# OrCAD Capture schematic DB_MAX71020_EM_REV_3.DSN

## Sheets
1 01. Revision History and Notes: title: DB71020 - Revision History and Notes; rev: 2.0; note: ART3 Utility; note: Copyright © 2014 - Maxim Integrated Products
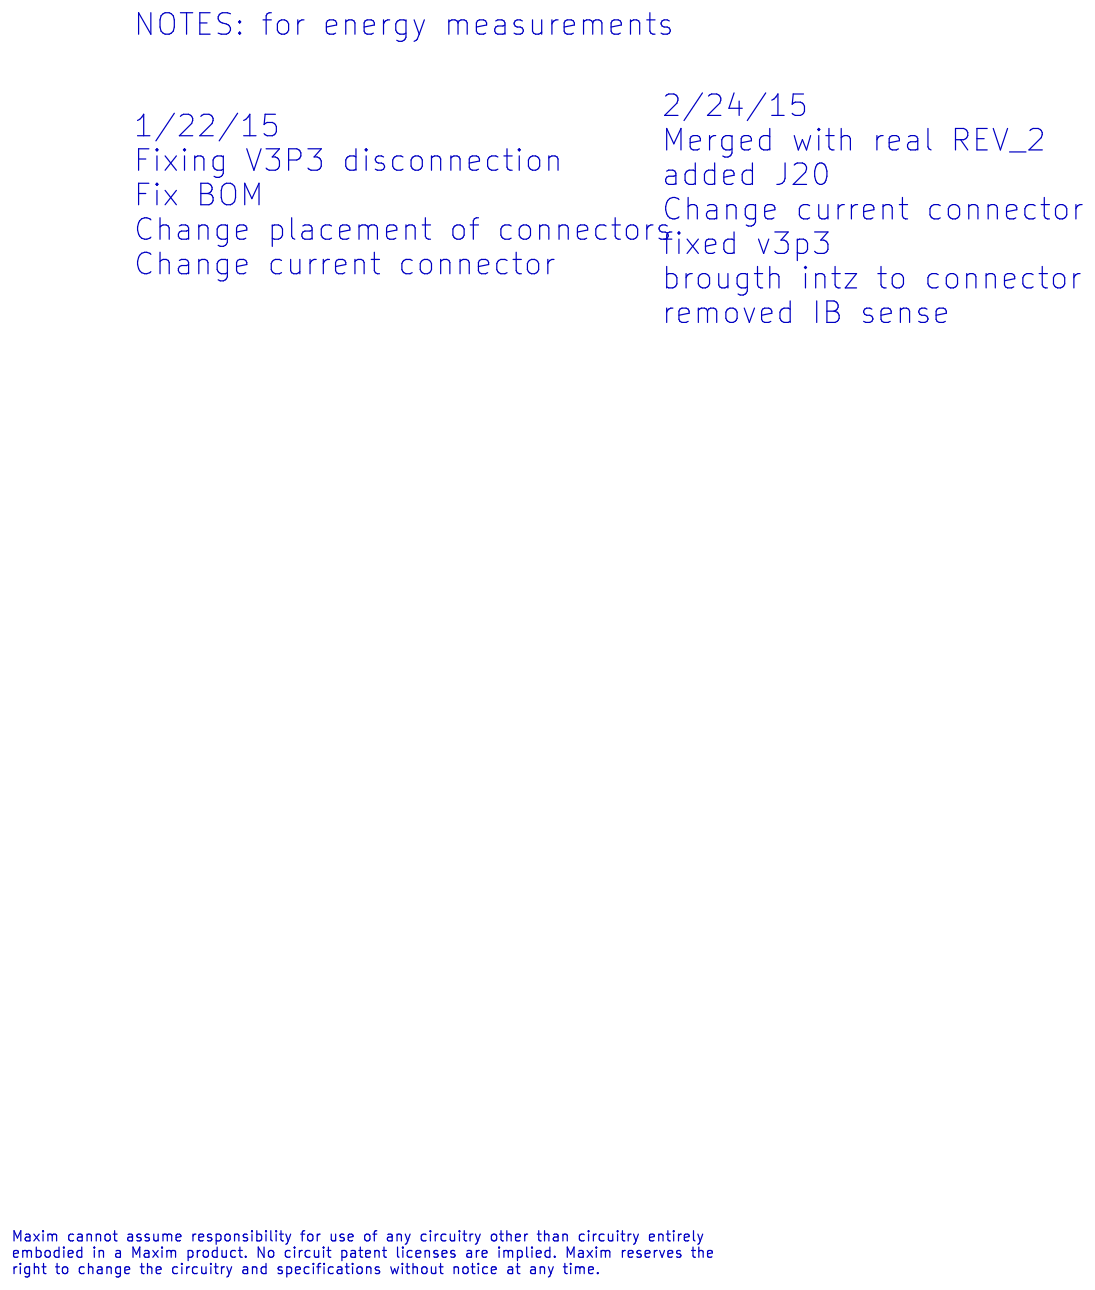
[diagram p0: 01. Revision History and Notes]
2 02. MAX71020: size B; title: DB71020 - AM48; rev: A
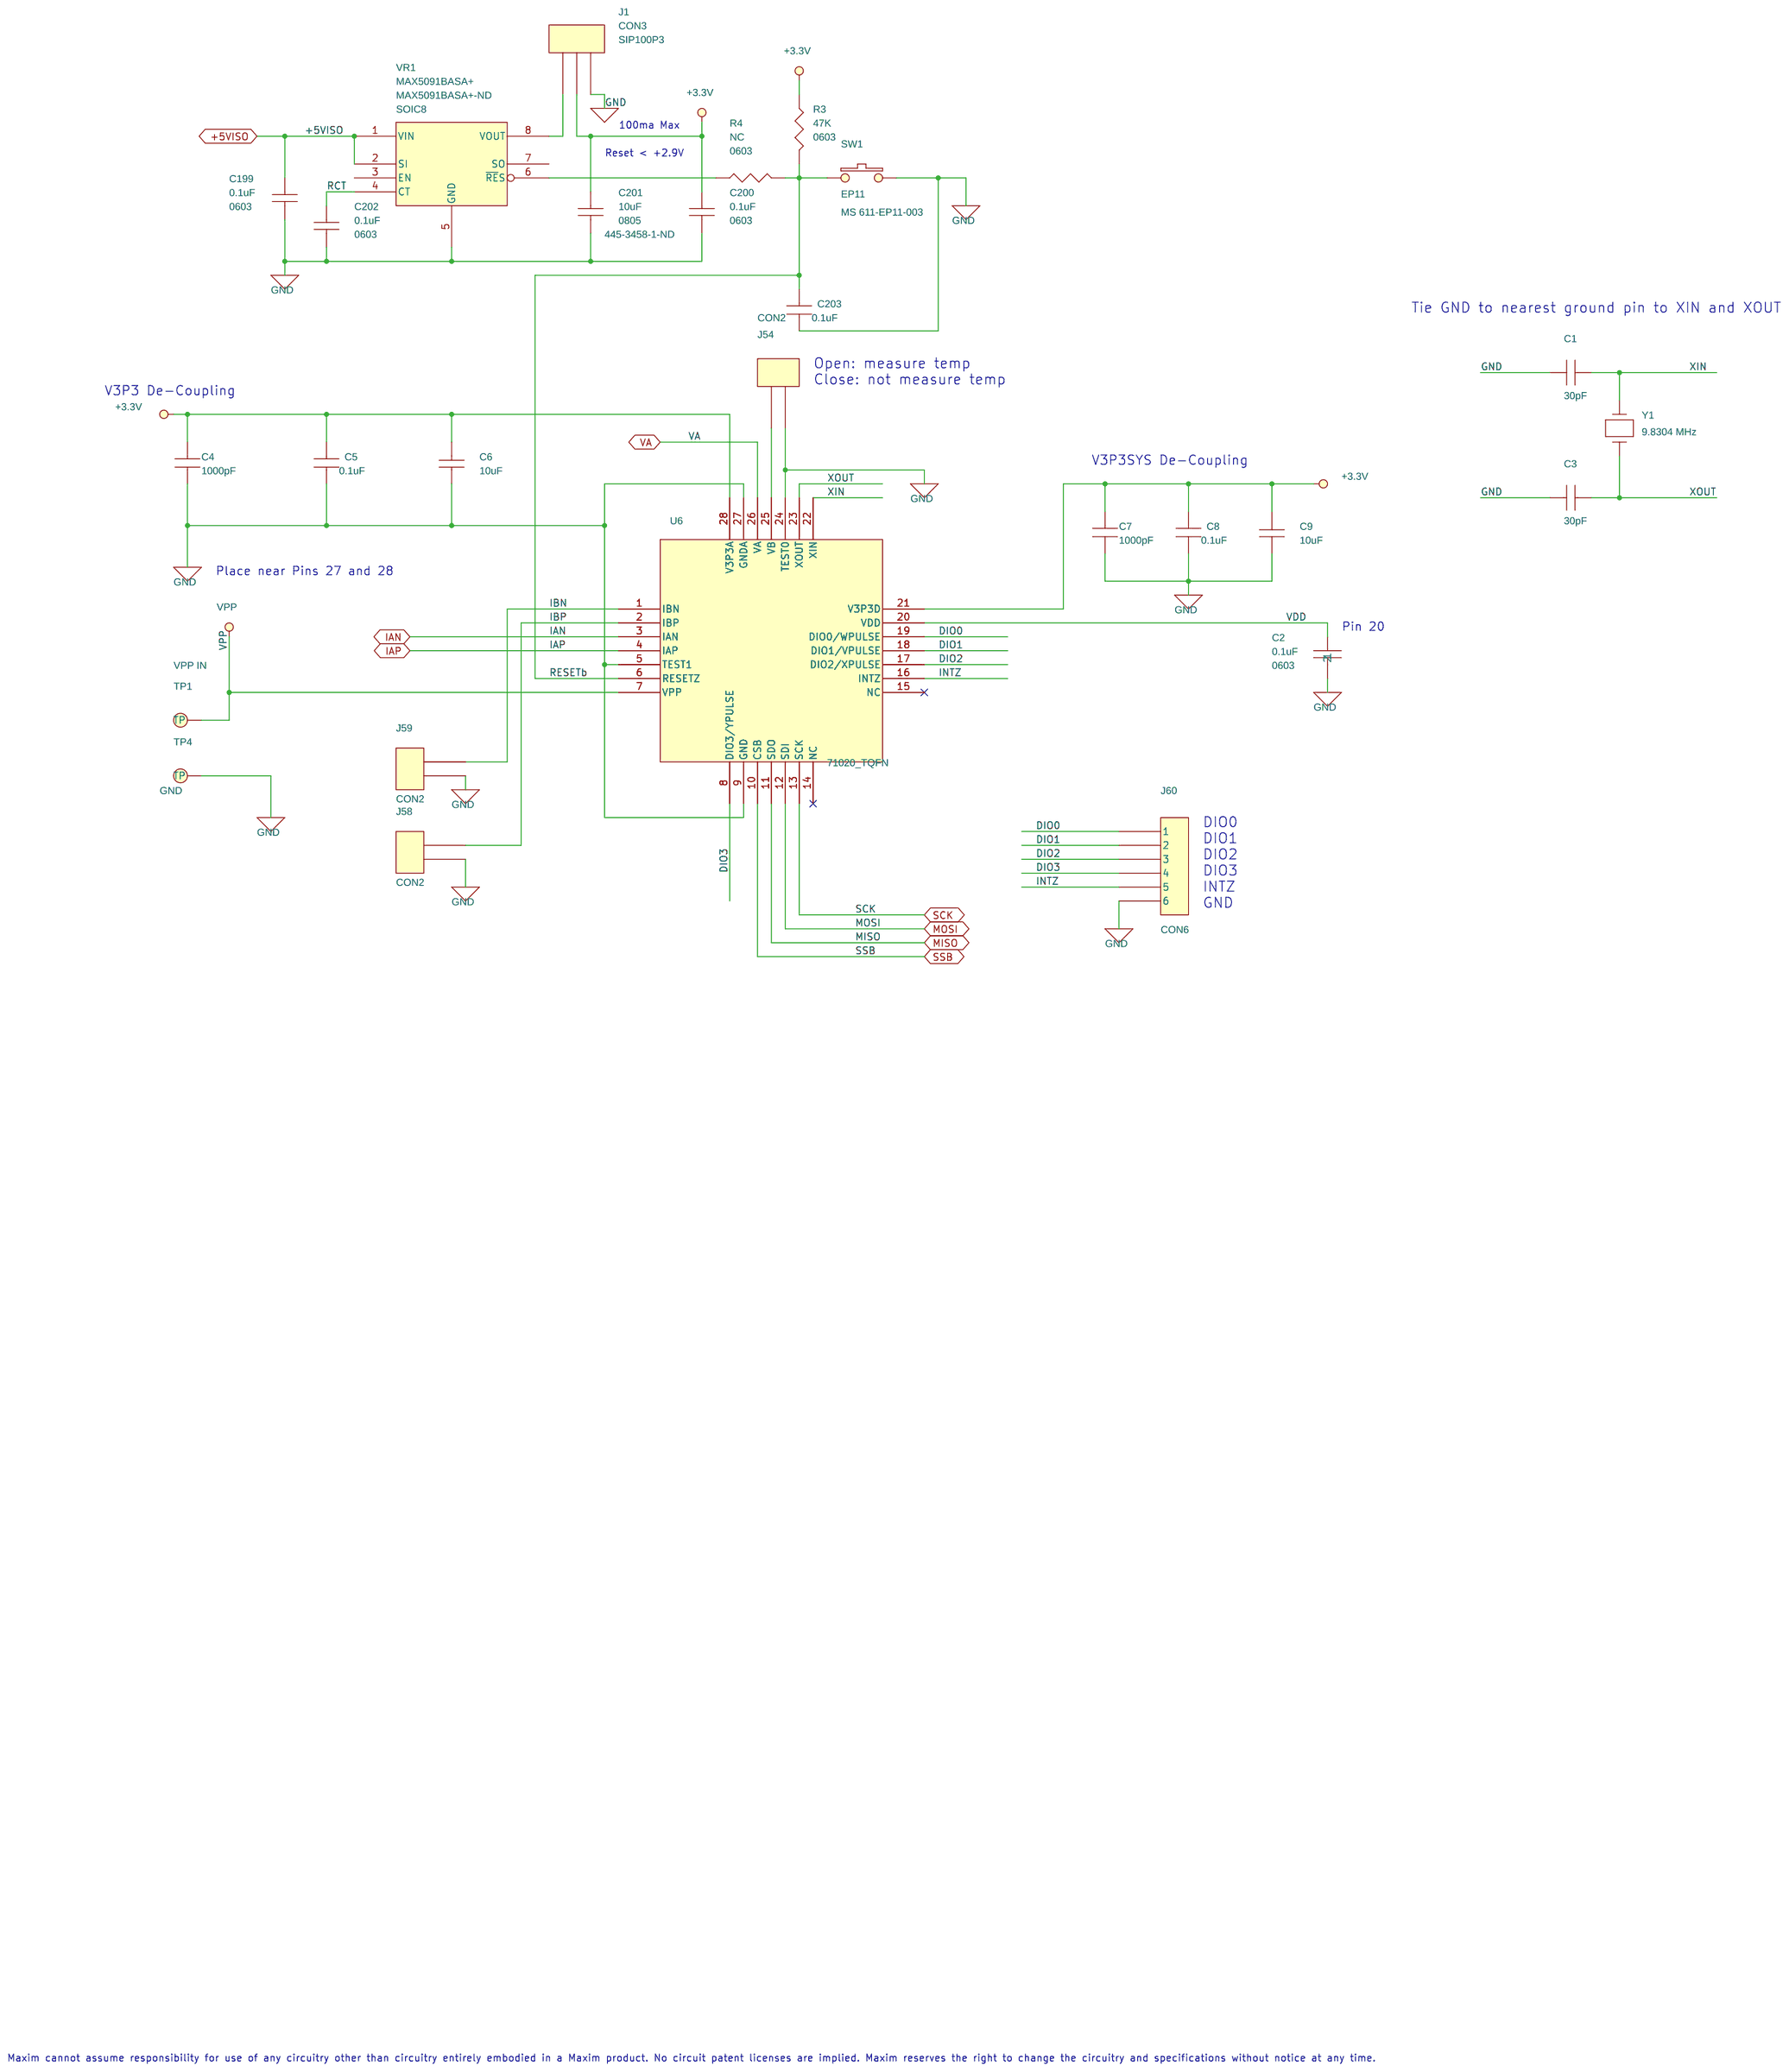
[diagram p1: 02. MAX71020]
3 03. Isolated USB to UART: size B; title: DB71020 - AM48
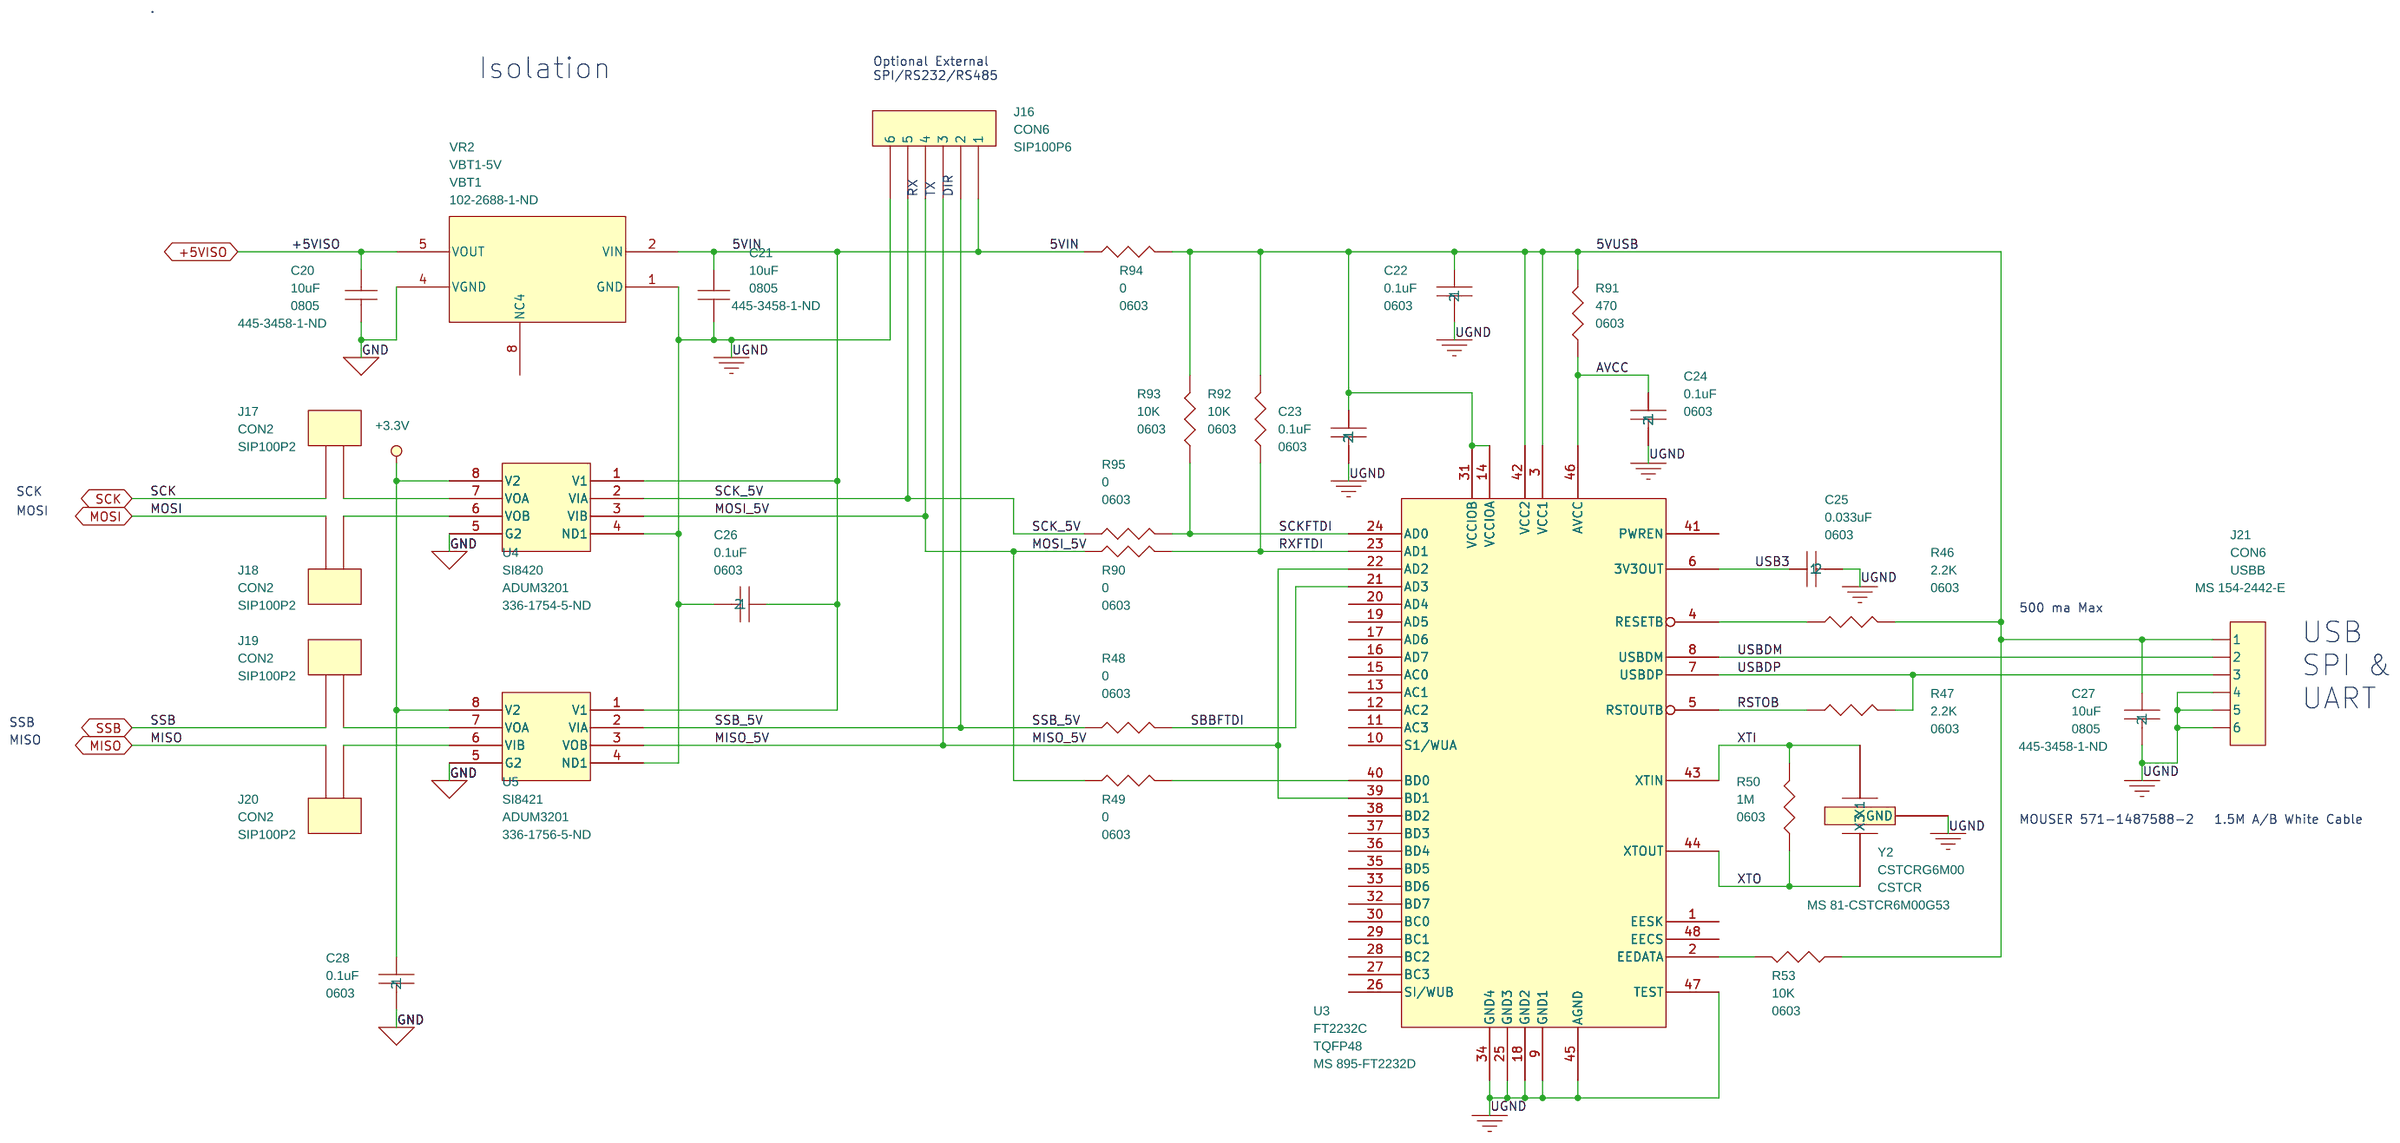
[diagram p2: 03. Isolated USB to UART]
4 04. Sensors: size Custom; title: DB71020 - Current & Voltage Sensors
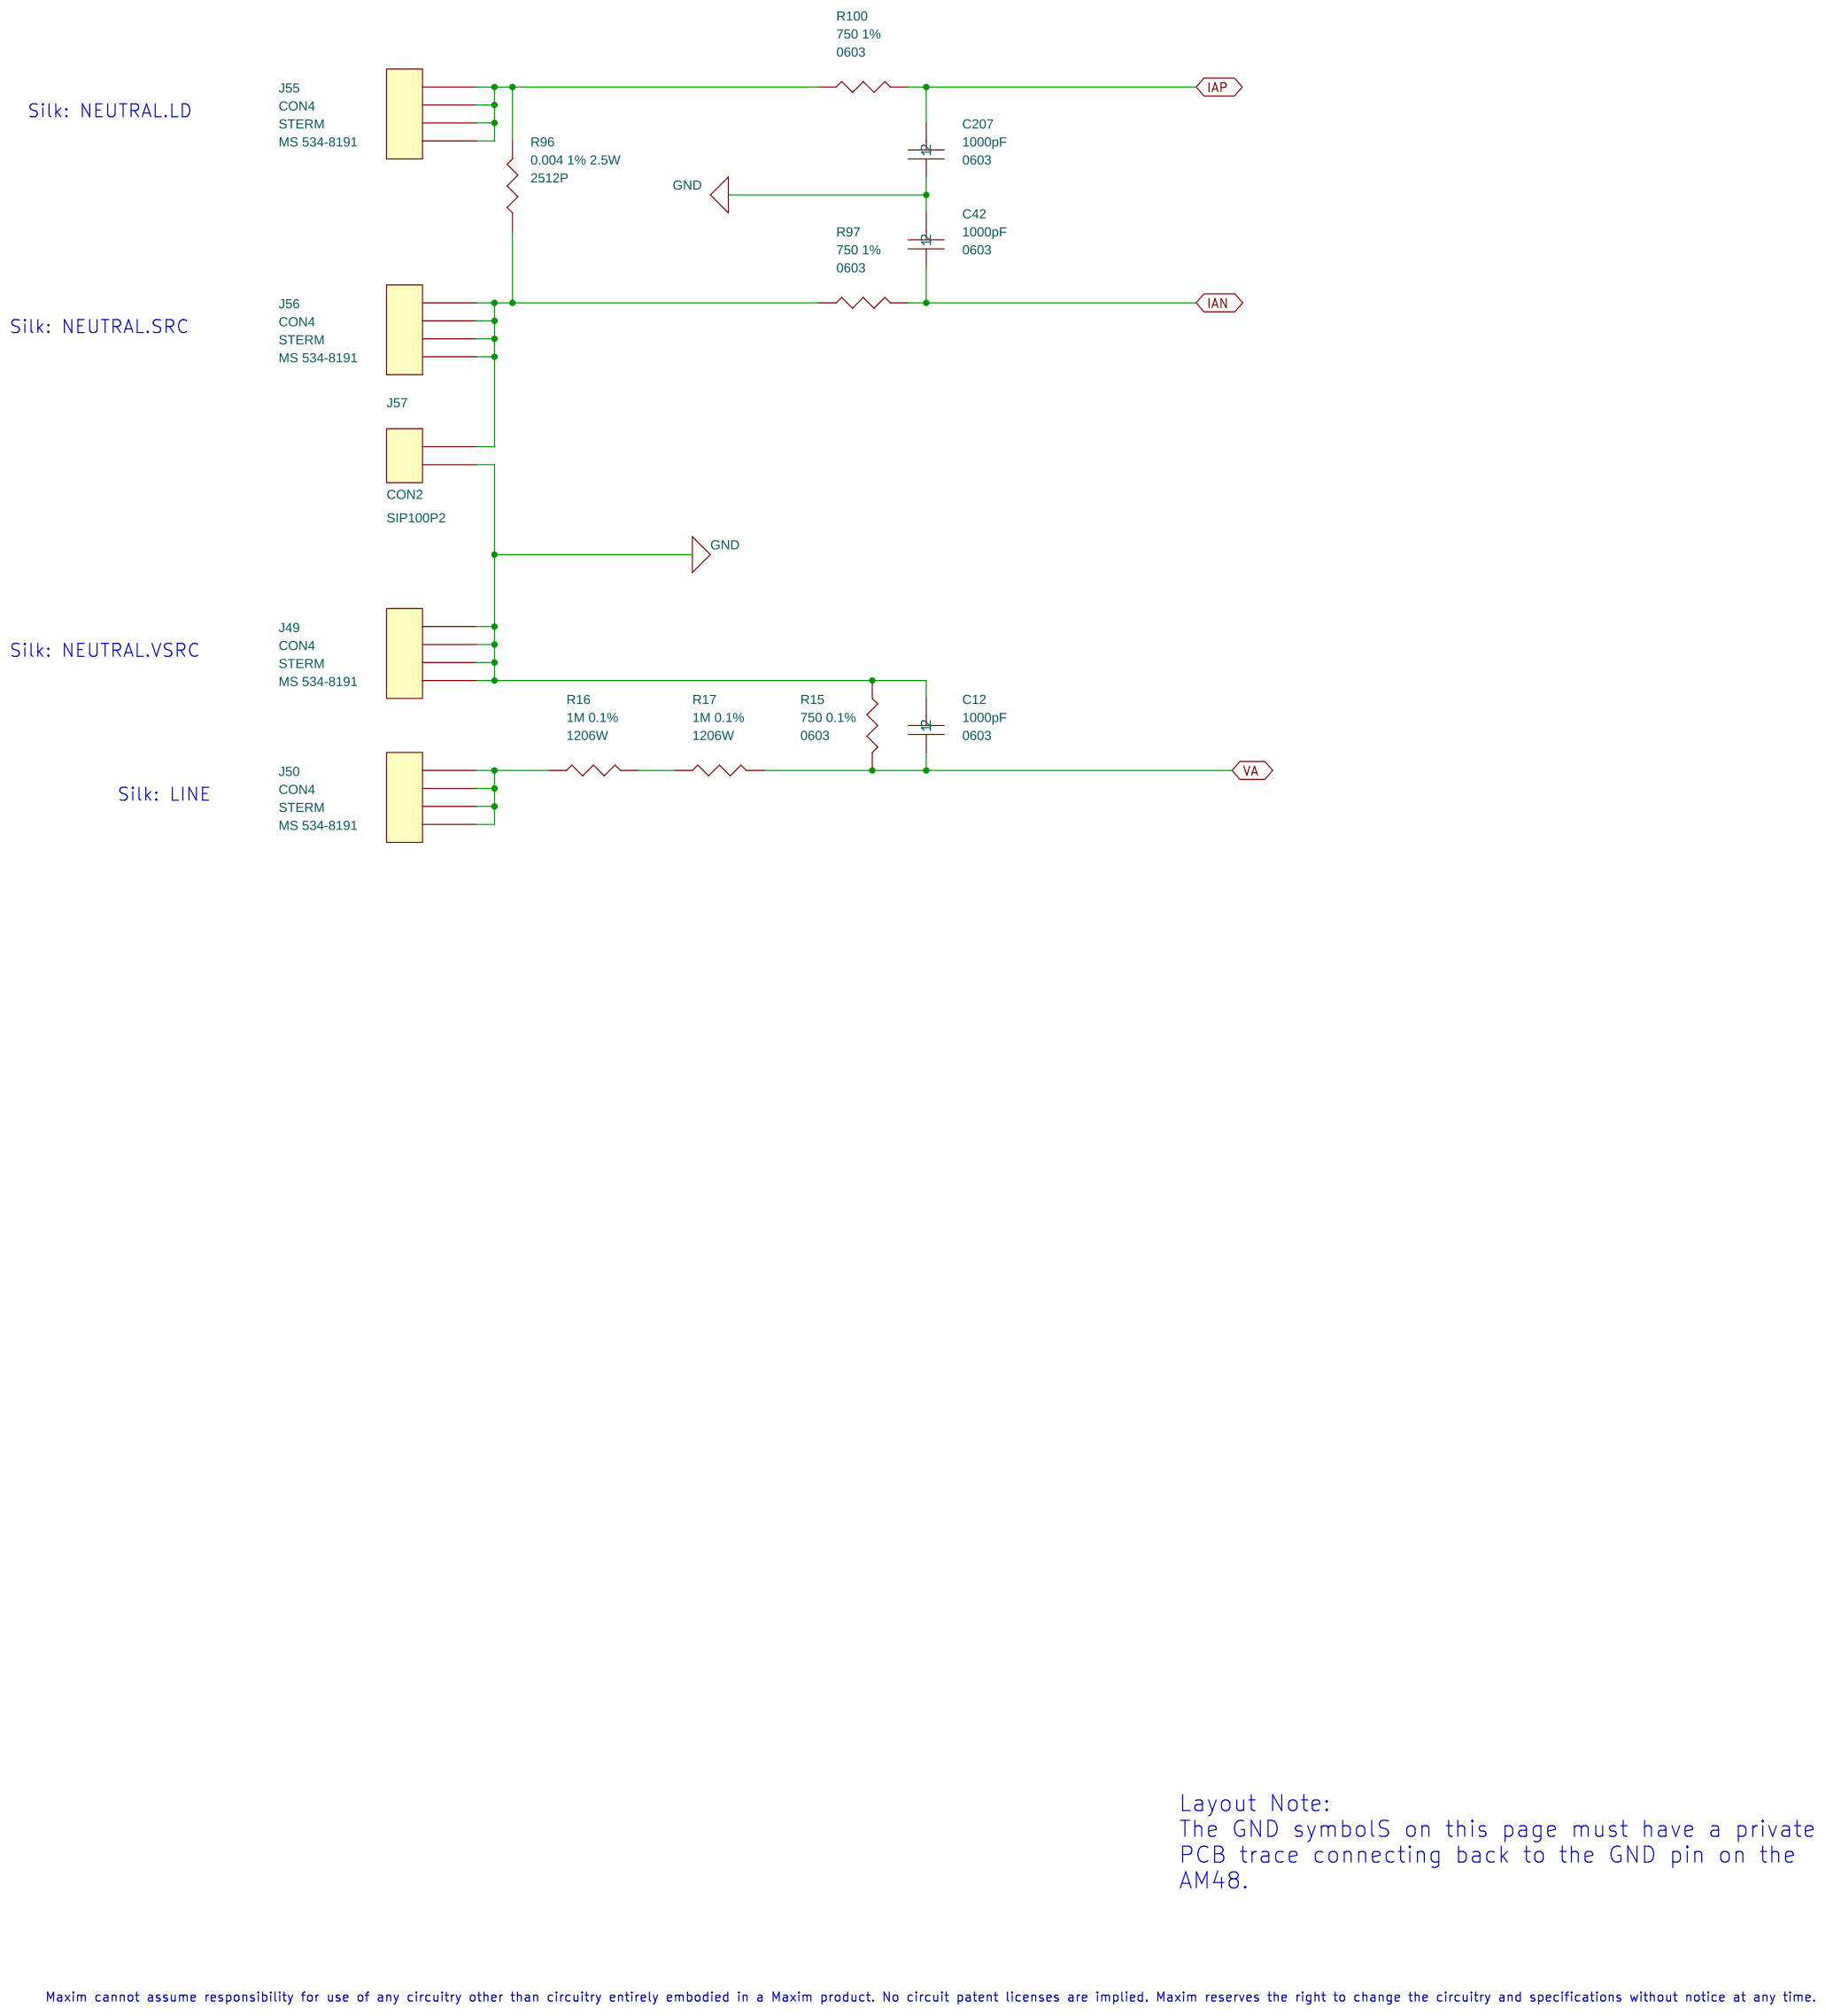
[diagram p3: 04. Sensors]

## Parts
sheet 02. MAX71020
C1  30pF  [CC0402_RLP100-N]
C2  0.1uF  [0603]
C3  30pF  [CC0402_RLP100-N]
C4  1000pF  [CC0402_RLP100-N]
C5  0.1uF  [CC0402_RLP100-N]
C6  10uF  [CC0603_RLP132-N]
C7  1000pF  [CC0402_RLP100-N]
C8  0.1uF  [CC0402_RLP100-N]
C9  10uF  [CC0603_RLP132-N]
C199  0.1uF  [0603]
C200  0.1uF  [0603]
C201  10uF  [0805]
C202  0.1uF  [0603]
C203  0.1uF  [CAPC1005(0402)56N]
J1  CON3  [SIP100P3]
J54  CON2
J58  CON2  [SIP/.1C/2P]
J59  CON2  [SIP/.1C/2P]
J60  CON6  [SIP/6P]
R3  47K  [0603]
R4  NC  [0603]
SW1  PUSHBUTTON  [EP11]
TP1  TP  [TP_500X_MINITURE]
TP4  TP  [TP_500X_MINITURE]
U6  71020_TQFN  [28TQFN]
VR1  MAX5091BASA+  [SOIC8]
Y1  9.8304 MHz  [XTAL_ABM7_6x3-5]
sheet 03. Isolated USB to UART
C20  10uF  [0805]
C21  10uF  [0805]
C22  0.1uF  [0603]
C23  0.1uF  [0603]
C24  0.1uF  [0603]
C25  0.033uF  [0603]
C26  0.1uF  [0603]
C27  10uF  [0805]
C28  0.1uF  [0603]
J16  CON6  [SIP100P6]
J17  CON2  [SIP100P2]
J18  CON2  [SIP100P2]
J19  CON2  [SIP100P2]
J20  CON2  [SIP100P2]
J21  CON6  [USBB]
R46  2.2K  [0603]
R47  2.2K  [0603]
R48  0  [0603]
R49  0  [0603]
R50  1M  [0603]
R53  10K  [0603]
R90  0  [0603]
R91  470  [0603]
R92  10K  [0603]
R93  10K  [0603]
R94  0  [0603]
R95  0  [0603]
U3  FT2232C  [TQFP48]
U4  SI8420  [ADUM3201]
U5  SI8421  [ADUM3201]
VR2  VBT1-5V  [VBT1]
Y2  CSTCRG6M00  [CSTCR]
sheet 04. Sensors
C12  1000pF  [0603]
C42  1000pF  [0603]
C207  1000pF  [0603]
J49  CON4  [STERM]
J50  CON4  [STERM]
J55  CON4  [STERM]
J56  CON4  [STERM]
J57  CON2  [SIP100P2]
R15  750 0.1%  [0603]
R16  1M 0.1%  [1206W]
R17  1M 0.1%  [1206W]
R96  0.004 1% 2.5W  [2512P]
R97  750 1%  [0603]
R100  750 1%  [0603]

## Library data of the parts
C1 C3 = CAPACITOR_NON-POL_3: BOM_Description: CAP CER 30PF 50V 5% NP0 0402; BOM_Manufacturer_PN: GRM1555C1H300JZ01D; BOM_Package: 0402; BOM_Vendor_PN: 490-1285-1-ND; COMPFIXED: NO; COMPGROUP: 0; COMPHEIGHT: 40.000; COMPKEY: NO; COMPLOC: [3355.000,3310.000]; COMPLOCKED: NO; COMPROT: 180; COMPSIDE: TOP; DECOUPLER: NO; Dielectric: C0G, NP0; MEMORY: NO; Manufacturer: Murata; Rating: 50V; SIGNAL_MODEL: DEFAULT_CAPACITOR_30pF_1_2; Tolerance: ±5%
C2 C24 = C: COMPFIXED: NO; COMPGROUP: 0; COMPHEIGHT: 0.000; COMPKEY: NO; COMPLOC: [3926.000,227.000]; COMPLOCKED: NO; COMPROT: 90; COMPSIDE: TOP; DECOUPLER: NO; FPLIST: BP805,0805; MEMORY: NO; SIGNAL_MODEL: DEFAULT_CAPACITOR_100000pF_1_2
C4 C7 = CAPACITOR_NON-POL_3: BOM_Description: CAP CER 1000PF 100V 10% X7R 0402; BOM_Manufacturer_PN: GCM155R72A102KA37D; BOM_Package: 0402; BOM_Vendor_PN: 490-4764-1-ND; COMPFIXED: NO; COMPGROUP: 0; COMPHEIGHT: 40.000; COMPKEY: NO; COMPLOC: [3155.000,3185.000]; COMPLOCKED: NO; COMPROT: 180; COMPSIDE: BOT; DECOUPLER: NO; Dielectric: X7R; MEMORY: NO; Manufacturer: Murata; Rating: 100V; SIGNAL_MODEL: DEFAULT_CAPACITOR_1000pF_1_2; Tolerance: ±10%
C5 C8 C203 = CAPACITOR_NON-POL_3: BOM_Description: CAP CER 0.1UF 50V 10% X7R 0402; BOM_Manufacturer_PN: C1005X7R1H104K; BOM_Package: 0402; BOM_Vendor_PN: 445-5932-1-ND; COMPFIXED: NO; COMPGROUP: 0; COMPHEIGHT: 40.000; COMPKEY: NO; COMPLOC: [3155.000,3260.000]; COMPLOCKED: NO; COMPROT: 0; COMPSIDE: BOT; DECOUPLER: NO; Dielectric: X7R; MEMORY: NO; Manufacturer: TDK; Rating: 50V; SIGNAL_MODEL: DEFAULT_CAPACITOR_100000pF_1_2; Tolerance: ±10%
C6 C9 = CAP_NP: BOM_Description: CAP CER 10UF 6.3V 20% X5R 0603; BOM_Manufacturer_PN: JMK107BJ106MA-T; BOM_Package: 0603; BOM_Vendor_PN: 587-1256-1-ND; COMPFIXED: NO; COMPGROUP: 0; COMPHEIGHT: 50.000; COMPKEY: NO; COMPLOC: [3680.000,3210.000]; COMPLOCKED: NO; COMPROT: 90; COMPSIDE: BOT; DECOUPLER: NO; Dielectric: X5R; MEMORY: NO; Manufacturer: Taiyo Yuden; Rating: 6.3V; SIGNAL_MODEL: DEFAULT_CAPACITOR_1e+07pF_1_2; Tolerance: ±10%
C199 = CAP_NP: COMPFIXED: NO; COMPGROUP: 0; COMPHEIGHT: 0.000; COMPKEY: NO; COMPLOC: [-1552.000,1919.000]; COMPLOCKED: NO; COMPROT: 0; COMPSIDE: TOP; DECOUPLER: NO; MEMORY: NO; SIGNAL_MODEL: DEFAULT_CAPACITOR_100000pF_1_2
C200 = CAP_NP: COMPFIXED: NO; COMPGROUP: 0; COMPHEIGHT: 0.000; COMPKEY: NO; COMPLOC: [-647.000,1569.000]; COMPLOCKED: NO; COMPROT: 0; COMPSIDE: TOP; DECOUPLER: NO; MEMORY: NO; SIGNAL_MODEL: DEFAULT_CAPACITOR_100000pF_1_2
C201 = CAP_NP: COMPFIXED: NO; COMPGROUP: 0; COMPHEIGHT: 0.000; COMPKEY: NO; COMPLOC: [-1270.000,2619.000]; COMPLOCKED: NO; COMPROT: 0; COMPSIDE: TOP; DECOUPLER: NO; DigiKey: 445-3458-1-ND; MEMORY: NO; SIGNAL_MODEL: DEFAULT_CAPACITOR_1e+07pF_1_2
C202 = CAP_NP: COMPFIXED: NO; COMPGROUP: 0; COMPHEIGHT: 0.000; COMPKEY: NO; COMPLOC: [-1900.000,800.000]; COMPLOCKED: NO; COMPROT: 0; COMPSIDE: TOP; DECOUPLER: NO; MEMORY: NO; SIGNAL_MODEL: DEFAULT_CAPACITOR_100000pF_1_2
J1 = CON3
J17-J20 J54 J57-J59 = CON2
J16 J60 = CON6
R3 = R: COMPFIXED: NO; COMPGROUP: 0; COMPHEIGHT: 0.000; COMPKEY: NO; COMPLOC: [700.000,1475.000]; COMPLOCKED: NO; COMPROT: 90; COMPSIDE: TOP; DECOUPLER: NO; MEMORY: NO; SIGNAL_MODEL: DEFAULT_RESISTOR_47000OHM_1_2
R4 = RESISTOR: COMPFIXED: NO; COMPGROUP: 0; COMPHEIGHT: 0.000; COMPKEY: NO; COMPLOC: [6150.000,730.000]; COMPLOCKED: NO; COMPROT: 180; COMPSIDE: TOP; DECOUPLER: NO; MEMORY: NO; PART NUMBER: ERJ-6ENF7500V; SIGNAL_MODEL: DEFAULT_RESISTOR_0.001OHM_1_2
SW1 = SW_PUSHBUTTON-SPST_SM: COMPFIXED: NO; COMPGROUP: 0; COMPHEIGHT: 0.000; COMPKEY: NO; COMPLOC: [3100.000,950.000]; COMPLOCKED: NO; COMPROT: 0; COMPSIDE: TOP; DECOUPLER: NO; DigiKey: MS 611-EP11-003; MEMORY: NO; Mouser: 611-EP11-003
TP1 = T_POINT_R: AUX_Silkscreen: VPP; BOM_Description: TEST POINT PC MINI .040"D WHITE; BOM_Manufacturer_PN: 5002; BOM_Vendor_PN: 5002K-ND; COMPFIXED: NO; COMPGROUP: 0; COMPHEIGHT: 180.000; COMPKEY: NO; COMPLOC: [5145.000,4105.000]; COMPLOCKED: NO; COMPROT: 0; COMPSIDE: BOT; DECOUPLER: NO; MEMORY: NO; Manufacturer: KEYSTONE; Silkscreen: VPP IN
TP4 = T_POINT_R: AUX_Silkscreen: GND; BOM_Description: TEST POINT PC MINI .040"D BLACK; BOM_Manufacturer_PN: 5001; BOM_Vendor_PN: 5001K-ND; COMPFIXED: NO; COMPGROUP: 0; COMPHEIGHT: 320.000; COMPKEY: NO; COMPLOC: [3200.000,2950.000]; COMPLOCKED: NO; COMPROT: 0; COMPSIDE: BOT; DECOUPLER: NO; MEMORY: NO; Manufacturer: KEYSTONE; Silkscreen: GND
U6 = 71020_TQFN
VR1 = MAX5091: COMPFIXED: NO; COMPGROUP: 0; COMPHEIGHT: 0.000; COMPKEY: NO; COMPLOC: [-2050.000,2175.000]; COMPLOCKED: NO; COMPROT: 0; COMPSIDE: TOP; DECOUPLER: NO; DigiKey: MAX5091BASA+-ND; MEMORY: NO
Y1 = CRYSTAL_0: BOM_Description: CRYSTAL 9.8304 MHZ 18PF SMD; BOM_Manufacturer_PN: ABM7-9.8304MHZ-D-2-Y-T; BOM_Package: 6.0mm x 3.5mm; BOM_Vendor_PN: 535-9832-1-ND; COMPFIXED: NO; COMPGROUP: 0; COMPHEIGHT: 22.000; COMPKEY: NO; COMPLOC: [3430.000,3435.000]; COMPLOCKED: NO; COMPROT: 180; COMPSIDE: TOP; DECOUPLER: NO; MEMORY: NO; Manufacturer: Abracom; Rating: 30ppm
C20 C21 = CAP_NP: COMPFIXED: NO; COMPGROUP: 0; COMPHEIGHT: 0.000; COMPKEY: NO; COMPLOC: [-1004.000,2619.000]; COMPLOCKED: NO; COMPROT: 0; COMPSIDE: TOP; DECOUPLER: NO; DigiKey: 445-3458-1-ND; MEMORY: NO; SIGNAL_MODEL: DEFAULT_CAPACITOR_1e+07pF_1_2
C22 = C_3: COMPFIXED: NO; COMPGROUP: 0; COMPHEIGHT: 0.000; COMPKEY: NO; COMPLOC: [3926.000,227.000]; COMPLOCKED: NO; COMPROT: 90; COMPSIDE: TOP; DECOUPLER: NO; FPLIST: BP805,0805; MEMORY: NO; SIGNAL_MODEL: DEFAULT_CAPACITOR_100000pF_1_2
C23 = C_2: COMPFIXED: NO; COMPGROUP: 0; COMPHEIGHT: 0.000; COMPKEY: NO; COMPLOC: [3926.000,227.000]; COMPLOCKED: NO; COMPROT: 90; COMPSIDE: TOP; DECOUPLER: NO; FPLIST: BP805,0805; MEMORY: NO; SIGNAL_MODEL: DEFAULT_CAPACITOR_100000pF_1_2
C25 = C_5: COMPFIXED: NO; COMPGROUP: 0; COMPHEIGHT: 0.000; COMPKEY: NO; COMPLOC: [3926.000,227.000]; COMPLOCKED: NO; COMPROT: 90; COMPSIDE: TOP; DECOUPLER: NO; FPLIST: BP805,0805; MEMORY: NO; SIGNAL_MODEL: DEFAULT_CAPACITOR_33000pF_1_2
C26 = C_1: COMPFIXED: NO; COMPGROUP: 0; COMPHEIGHT: 0.000; COMPKEY: NO; COMPLOC: [4610.000,2790.000]; COMPLOCKED: NO; COMPROT: 90; COMPSIDE: BOT; DECOUPLER: NO; FPLIST: 0805; MEMORY: NO; PART NUMBER: C1608X7R1H104K; SIGNAL_MODEL: DEFAULT_CAPACITOR_100000pF_1_2
C27 = C_6: COMPFIXED: NO; COMPGROUP: 0; COMPHEIGHT: 0.000; COMPKEY: NO; COMPLOC: [3926.000,227.000]; COMPLOCKED: NO; COMPROT: 90; COMPSIDE: TOP; DECOUPLER: NO; DigiKey: 445-3458-1-ND; FPLIST: BP805,0805; MEMORY: NO; SIGNAL_MODEL: DEFAULT_CAPACITOR_1e+07pF_1_2
C28 = C_4: COMPFIXED: NO; COMPGROUP: 0; COMPHEIGHT: 0.000; COMPKEY: NO; COMPLOC: [4610.000,2790.000]; COMPLOCKED: NO; COMPROT: 90; COMPSIDE: BOT; DECOUPLER: NO; FPLIST: 0805; MEMORY: NO; PART NUMBER: C1608X7R1H104K; SIGNAL_MODEL: DEFAULT_CAPACITOR_100000pF_1_2
J21 = CON6_v2: DigiKey: MS 154-2442-E
R46 R47 = RESISTOR: COMPFIXED: NO; COMPGROUP: 0; COMPHEIGHT: 0.000; COMPKEY: NO; COMPLOC: [298.000,1908.000]; COMPLOCKED: NO; COMPROT: 180; COMPSIDE: TOP; DECOUPLER: NO; FPLIST: 0805; MEMORY: NO; SIGNAL_MODEL: DEFAULT_RESISTOR_2200OHM_1_2
R48 R49 R90 R94 R95 = RESISTOR: COMPFIXED: NO; COMPHEIGHT: 0.000; COMPKEY: NO; COMPLOC: [298.000,1908.000]; COMPLOCKED: NO; COMPROT: 180; COMPSIDE: TOP; DECOUPLER: NO; FPLIST: 0805; MEMORY: NO; SIGNAL_MODEL: DEFAULT_RESISTOR_0.001OHM_1_2
R50 = RESISTOR: COMPFIXED: NO; COMPGROUP: 0; COMPHEIGHT: 0.000; COMPKEY: NO; COMPLOC: [298.000,1908.000]; COMPLOCKED: NO; COMPROT: 180; COMPSIDE: TOP; DECOUPLER: NO; FPLIST: 0805; MEMORY: NO; SIGNAL_MODEL: DEFAULT_RESISTOR_1OHM_1_2
R53 R92 R93 = RESISTOR: COMPFIXED: NO; COMPGROUP: 0; COMPHEIGHT: 0.000; COMPKEY: NO; COMPLOC: [298.000,1908.000]; COMPLOCKED: NO; COMPROT: 180; COMPSIDE: TOP; DECOUPLER: NO; FPLIST: 0805; MEMORY: NO; SIGNAL_MODEL: DEFAULT_RESISTOR_10000OHM_1_2
R91 = RESISTOR: COMPFIXED: NO; COMPGROUP: 0; COMPHEIGHT: 0.000; COMPKEY: NO; COMPLOC: [298.000,1908.000]; COMPLOCKED: NO; COMPROT: 180; COMPSIDE: TOP; DECOUPLER: NO; FPLIST: 0805; MEMORY: NO; SIGNAL_MODEL: DEFAULT_RESISTOR_470OHM_1_2
U3 = FT2232C: DigiKey: MS 895-FT2232D
U4 = ADUM3201_2: COMPFIXED: NO; COMPGROUP: 0; COMPHEIGHT: 0.000; COMPKEY: NO; COMPLOC: [2425.000,2400.000]; COMPLOCKED: NO; COMPROT: 270; COMPSIDE: TOP; DECOUPLER: NO; DigiKey: 336-1754-5-ND; MEMORY: NO; Mouser: DigiKey ADUM3201ARZ-ND
U5 = ADUM3201_3: COMPFIXED: NO; COMPGROUP: 0; COMPHEIGHT: 0.000; COMPKEY: NO; COMPLOC: [2425.000,2400.000]; COMPLOCKED: NO; COMPROT: 270; COMPSIDE: TOP; DECOUPLER: NO; DigiKey: 336-1756-5-ND; MEMORY: NO; Mouser: DigiKey ADUM3201ARZ-ND
VR2 = VBT1-5V_0: COMPFIXED: NO; COMPGROUP: 0; COMPHEIGHT: 0.000; COMPKEY: NO; COMPLOC: [2375.000,2700.000]; COMPLOCKED: NO; COMPROT: 0; COMPSIDE: TOP; DECOUPLER: NO; DigiKey: 102-2688-1-ND; MEMORY: NO; MFR: CUI Inc.; MFR Part#: PDS1-S5-S5-M-TR
Y2 = CSTCRG6M00: DigiKey: MS 81-CSTCR6M00G53
C12 = C_2: COMPFIXED: NO; COMPGROUP: 0; COMPHEIGHT: 0.000; COMPKEY: NO; COMPLOC: [-1475.000,19750.000]; COMPLOCKED: NO; COMPROT: 180; COMPSIDE: BOT; DECOUPLER: NO; FPLIST: 0805; MEMORY: NO; SIGNAL_MODEL: DEFAULT_CAPACITOR_1000pF_1_2
C42 = C_1: COMPFIXED: NO; COMPGROUP: 0; COMPHEIGHT: 0.000; COMPKEY: NO; COMPLOC: [-1475.000,19750.000]; COMPLOCKED: NO; COMPROT: 180; COMPSIDE: BOT; DECOUPLER: NO; FPLIST: 0805; MEMORY: NO; SIGNAL_MODEL: DEFAULT_CAPACITOR_1000pF_1_2
C207 = C: COMPFIXED: NO; COMPGROUP: 0; COMPHEIGHT: 0.000; COMPKEY: NO; COMPLOC: [-1475.000,19750.000]; COMPLOCKED: NO; COMPROT: 180; COMPSIDE: BOT; DECOUPLER: NO; FPLIST: 0805; MEMORY: NO; SIGNAL_MODEL: DEFAULT_CAPACITOR_1000pF_1_2
J49 J50 J55 J56 = CON4: DigiKey: MS 534-8191
R15 = RESISTOR: COMPFIXED: NO; COMPGROUP: 0; COMPHEIGHT: 0.000; COMPKEY: NO; COMPLOC: [4450.000,1610.000]; COMPLOCKED: NO; COMPROT: 90; COMPSIDE: TOP; DECOUPLER: NO; FPLIST: 0805; MEMORY: NO; SIGNAL_MODEL: DEFAULT_RESISTOR_0.75OHM_1_2
R16 = RESISTOR: COMPFIXED: NO; COMPGROUP: 0; COMPHEIGHT: 0.000; COMPKEY: NO; COMPLOC: [4150.000,1075.000]; COMPLOCKED: NO; COMPROT: 0; COMPSIDE: TOP; DECOUPLER: NO; DigiKey: MS 660-RN732BTTD1004B25; FPLIST: 0805; MEMORY: NO; Mouser: 660-RK73H3ATTE1004F; SIGNAL_MODEL: DEFAULT_RESISTOR_1OHM_1_2
R17 = RESISTOR: COMPFIXED: NO; COMPGROUP: 0; COMPHEIGHT: 0.000; COMPKEY: NO; COMPLOC: [4425.000,1275.000]; COMPLOCKED: NO; COMPROT: 180; COMPSIDE: TOP; DECOUPLER: NO; DigiKey: MS 660-RN732BTTD1004B25; FPLIST: 0805; MEMORY: NO; SIGNAL_MODEL: DEFAULT_RESISTOR_1OHM_1_2
R96 = RESISTOR: COMPFIXED: NO; COMPGROUP: 0; COMPHEIGHT: 0.000; COMPKEY: NO; COMPLOC: [1100.000,825.000]; COMPLOCKED: NO; COMPROT: 0; COMPSIDE: TOP; DECOUPLER: NO; DigiKey: MS 66-ULR25R004FLFTR; FPLIST: 1206,0805; MEMORY: NO; PART NUMBER: ERJ-8ENF7681V; SIGNAL_MODEL: DEFAULT_RESISTOR_0.004OHM_1_2
R97 R100 = RESISTOR: COMPFIXED: NO; COMPGROUP: 0; COMPHEIGHT: 0.000; COMPKEY: NO; COMPLOC: [6150.000,730.000]; COMPLOCKED: NO; COMPROT: 180; COMPSIDE: TOP; DECOUPLER: NO; MEMORY: NO; PART NUMBER: ERJ-6ENF7500V; SIGNAL_MODEL: DEFAULT_RESISTOR_7.5OHM_1_2

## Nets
5VIN: C21.1 C26.1 J16.1 R94.1 U4.1(V1) U5.1(V1) VR2.2(VIN)
5VUSB: C22.1 C23.1 C27.1 J21.1 R46.2 R53.1 R91.2 R92.2 R93.2 R94.2 U3.3(VCC1) U3.14(VCCIOA) U3.31(VCCIOB) U3.42(VCC2)
+3.3V: C4.2 C5.1 C6.2 C7.2 C8.1 C9.2 C28.1 C200.1 C201.1 J1.2 R3.1 U4.8(V2) U5.8(V2) U6.21(V3P3D) U6.28(V3P3A)
+5VISO: C20.1 C199.1 VR1.1(VIN) VR1.2(SI) VR2.5(VOUT)
AVCC: C24.1 R91.1 U3.46(AVCC)
GND: C1.1 C2.2 C3.1 C4.1 C5.2 C6.1 C7.1 C8.2 C9.1 C12.2 C20.2 C28.2 C42.2 C199.2 C200.2 C201.2 C202.2 C203.2 C207.1 J1.3 J49.1 J49.2 J49.3 J49.4 J54.1 J57.2 J58.2 J59.2 J60.6 R15.1 SW1.2 TP4.1(TP) U4.5(G2) U5.5(G2) U6.5(TEST1) U6.9(GND) U6.24(TEST0) U6.27(GNDA) VR1.5(GND) VR2.4(VGND)
GND_POWER: C21.2 C22.2 C23.2 C24.2 C25.2 C26.2 C27.2 J16.6 J21.4 J21.5 J21.6 U3.9(GND1) U3.18(GND2) U3.25(GND3) U3.34(GND4) U3.45(AGND) U3.47(TEST) U4.4(ND1) U5.4(ND1) VR2.1(GND) Y2.2(GND)
VDD: C2.1 U6.20(VDD)
DIO0: J60.1 U6.19(DIO0/WPULSE)
DIO1: J60.2 U6.18(DIO1/VPULSE)
DIO2: J60.3 U6.17(DIO2/XPULSE)
DIO3: J60.4 U6.8(DIO3/YPULSE)
IAN: C42.1 R97.2 U6.3(IAN)
IAP: C207.2 R100.2 U6.4(IAP)
IBN: J59.1 U6.1(IBN)
IBP: J58.1 U6.2(IBP)
INTZ: J60.5 U6.16(INTZ)
MISO: J20.2 U6.11(SDO)
MISO_5V: J16.3 U3.22(AD2) U3.39(BD1) U5.3(VOB)
MOSI: J18.2 U6.12(SDI)
MOSI_5V: J16.4 R49.2 R90.2 U4.3(VIB)
RCT: C202.1 VR1.4(CT)
RESETb: C203.1 R3.2 R4.2 SW1.1 U6.6(RESETZ)
RSTOB: R47.1 U3.5(RSTOUTB)
RXFTDI: R90.1 R92.1 U3.23(AD1)
SBBFTDI: R48.1 U3.21(AD3)
SCK: J17.2 U6.13(SCK)
SCK_5V: J16.5 R95.2 U4.2(VIA)
SCKFTDI: R93.1 R95.1 U3.24(AD0)
SSB: J19.2 U6.10(CSB)
SSB_5V: J16.2 R48.2 U5.2(VIA)
USB3: C25.1 U3.6(3V3OUT)
USBDM: J21.2 U3.8(USBDM)
USBDP: J21.3 R47.2 U3.7(USBDP)
VA: C12.1 R15.2 R17.2 U6.26(VA)
VPP: TP1.1(TP) U6.7(VPP)
XIN: C1.2 U6.22(XIN) Y1.2
XOUT: C3.2 U6.23(XOUT) Y1.1
XTI: R50.2 U3.43(XTIN) Y2.1(X1)
XTO: R50.1 U3.44(XTOUT) Y2.3(X3)
N16980473: R46.1 U3.4(RESETB)
N16980573: R49.1 U3.40(BD0)
N16980915: J18.1 U4.6(VOB)
N16981416: R53.2 U3.2(EEDATA)
N16981457: J17.1 U4.7(VOA)
N16981476: J19.1 U5.7(VOA)
N16986322: J1.1 VR1.8(VOUT)
N16986393: R4.1 VR1.6(~{RE}S)
N16992458: J54.2 U6.25(VB)
N16999058: J55.1 J55.2 J55.3 J55.4 R96.2 R100.1
N16999062: J56.1 J56.2 J56.3 J56.4 J57.1 R96.1 R97.1
N17000023: J50.1 J50.2 J50.3 J50.4 R16.1
N17000085: R16.2 R17.1
N17008974: J20.1 U5.6(VIB)

Not connected (* = marked no-connect by the designer): U3 1(EESK) 10(S1/WUA) 11(AC3) 12(AC2) 13(AC1) 15(AC0) 16(AD7) 17(AD6) 19(AD5) 20(AD4) 26(SI/WUB) 27(BC3) 28(BC2) 29(BC1) 30(BC0) 32(BD7) 33(BD6) 35(BD5) 36(BD4) 37(BD3) 38(BD2) 41(PWREN) 48(EECS); U6 14(NC)* 15(NC)*; VR1 3(EN) 7(SO); VR2 8(NC4)

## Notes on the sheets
sheet 1
- NOTES: for energy measurements
- 2/24/15
  Merged with real REV_2
  added J20
  Change current connector
  fixed v3p3
  brougth intz to connector
  removed IB sense
- 1/22/15
  Fixing V3P3 disconnection
  Fix BOM
  Change placement of connectors
  Change current connector
- Maxim cannot assume responsibility for use of any circuitry other than circuitry entirely
  embodied in a Maxim product. No circuit patent licenses are implied. Maxim reserves the
  right to change the circuitry and specifications without notice at any time.
sheet 2
- 100ma Max
- Reset < +2.9V
- Tie GND to nearest ground pin to XIN and XOUT
- Open: measure temp
  Close: not measure temp
- V3P3 De-Coupling
- V3P3SYS De-Coupling
- Place near Pins 27 and 28
- Pin 20
- DIO0
  DIO1
  DIO2
  DIO3
  INTZ
  GND
- Maxim cannot assume responsibility for use of any circuitry other than circuitry entirely embodied in a Maxim product. No circuit patent licenses are implied. Maxim reserves the right to change the circuitry and specifications without notice at any time.
sheet 3
- .
- Isolation
- Optional External
  SPI/RS232/RS485
- RX
- TX
- DIR
- SCK
- MOSI
- 500 ma Max
- USB
  SPI &
  UART
- SSB
- MISO
- MOUSER 571-1487588-2   1.5M A/B White Cable
sheet 4
- Silk: NEUTRAL.LD
- Silk: NEUTRAL.SRC
- Silk: NEUTRAL.VSRC
- Silk: LINE
- Layout Note:
  The GND symbolS on this page must have a private
  PCB trace connecting back to the GND pin on the
  AM48.
- Maxim cannot assume responsibility for use of any circuitry other than circuitry entirely embodied in a Maxim product. No circuit patent licenses are implied. Maxim reserves the right to change the circuitry and specifications without notice at any time.
